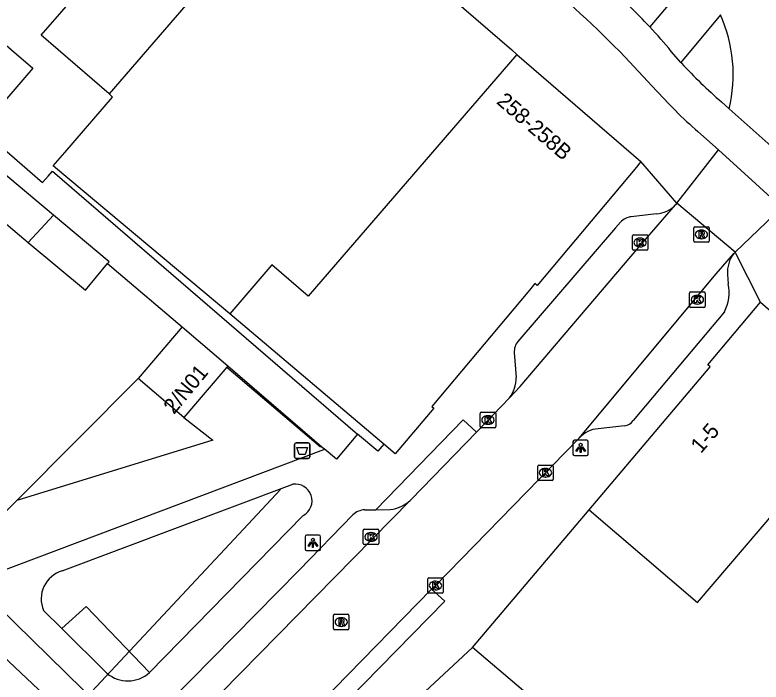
# Model space of a CAD drawing. Extents: x 162347 to 162868, y 381221 to 381813.
# Drawn here: x 162638.62 to 162687, y 381630.34 to 381673.56 of the extents above; entities that cross this region are included whole.
import ezdxf

# ---------------------------------------------------------------- set-up
doc = ezdxf.new("R2010")
doc.units = 0
for name, color, linetype in [('IMGEO_Afvalbak', 7, 'Continuous'), ('IMGEO_Fietspad_gesloten', 7, 'Continuous'), ('IMGEO_Groenvoorziening', 7, 'Continuous'), ('IMGEO_Hek', 7, 'Continuous'), ('IMGEO_Kolk', 7, 'Continuous'), ('IMGEO_Lichtpunt', 7, 'Continuous'), ('IMGEO_Pand', 7, 'Continuous'), ('IMGEO_Pand_nummerreeks', 7, 'Continuous'), ('IMGEO_Rijbaan_lokaal_gesloten', 7, 'Continuous'), ('IMGEO_Rijbaan_lokaal_open', 7, 'Continuous'), ('IMGEO_Rioolput', 7, 'Continuous'), ('IMGEO_Voetpad_open', 7, 'Continuous')]:
    doc.layers.add(name, color=color, linetype=linetype)

msp = doc.modelspace()

# ---------------------------------------------------------------- linework, layer by layer
at = {"layer": 'IMGEO_Afvalbak'}
for p, q in [((162656.75, 381644.93), (162656.75, 381645.73)), ((162656.75, 381645.73), (162656.75, 381644.93)), ((162656.85, 381645.83), (162657.64, 381645.83)), ((162657.64, 381645.83), (162656.85, 381645.83)), ((162657.74, 381645.73), (162657.74, 381644.93)), ((162657.74, 381644.93), (162657.74, 381645.73)), ((162657.64, 381644.83), (162656.85, 381644.83)), ((162656.85, 381644.83), (162657.64, 381644.83))]:
    msp.add_line(p, q, dxfattribs=at)
msp.add_lwpolyline([(162656.893, 381645.544), (162657.597, 381645.544), (162657.448, 381645.074), (162657.042, 381645.074), (162656.893, 381645.544)], dxfattribs=at)
for centre, start, end in [((162656.85, 381645.73), 90, 180), ((162656.85, 381645.73), 90, 180), ((162657.64, 381645.73), 0, 90), ((162657.64, 381645.73), 360, 90), ((162656.85, 381644.93), 180, 270), ((162656.85, 381644.93), 180, 270), ((162657.64, 381644.93), 270, 0), ((162657.64, 381644.93), 270, 0)]:
    msp.add_arc(centre, 0.1, start, end, dxfattribs=at)
at = {"layer": 'IMGEO_Fietspad_gesloten'}
for points in [[(162681.795, 381670.488), (162681.178, 381671.194)], [(162680.247, 381668.629), (162678.17, 381670.854)], [(162681.84, 381670.436), (162681.795, 381670.488)], [(162684.935, 381667.487), (162684.428, 381667.923)], [(162684.232, 381664.825), (162683.099, 381665.838)]]:
    msp.add_lwpolyline(points, dxfattribs=at)
for centre, radius, start, end in [((162612.48, 381606.111), 92.232, 44.58423, 49.55754), ((162653.024, 381647.945), 36.514, 42.8755, 48.9472), ((162652.152, 381647.216), 37.649, 39.5606, 42.7858), ((162707.177, 381693.941), 34.561, 222.8508, 228.8339), ((162701.917, 381687.92), 29.013, 221.676, 229.5626)]:
    msp.add_arc(centre, radius, start, end, dxfattribs=at)
at = {"layer": 'IMGEO_Groenvoorziening'}
for points in [[(162646.61, 381650.012), (162638.739, 381642.093)], [(162649.564, 381647.48), (162651.445, 381646.012), (162638.739, 381642.093)], [(162638.739, 381642.093), (162637.13, 381640.474), (162633.056, 381636.194)], [(162647.35, 381630.961), (162643.234, 381635.23), (162641.661, 381633.808)]]:
    msp.add_lwpolyline(points, dxfattribs=at)
at = {"layer": 'IMGEO_Hek'}
for points in [[(162652.358, 381650.739), (162658.431, 381645.579)], [(162655.842, 381642.815), (162652.232, 381638.954)], [(162652.232, 381638.954), (162642.062, 381628.072), (162636.69, 381633.102)]]:
    msp.add_lwpolyline(points, dxfattribs=at)
at = {"layer": 'IMGEO_Kolk'}
for p, q in [((162678.652, 381658.392), (162678.652, 381659.244)), ((162678.727, 381659.318), (162679.579, 381659.318)), ((162679.14, 381659.098), (162679.165, 381659.098)), ((162679.653, 381659.244), (162679.653, 381658.392)), ((162679.163, 381658.538), (162679.138, 381658.538)), ((162679.579, 381658.318), (162678.727, 381658.318)), ((162682.442, 381655.611), (162683.294, 381655.611)), ((162682.367, 381654.685), (162682.367, 381655.537)), ((162682.855, 381655.391), (162682.88, 381655.391)), ((162683.368, 381655.537), (162683.368, 381654.685)), ((162683.294, 381654.611), (162682.442, 381654.611)), ((162682.878, 381654.831), (162682.853, 381654.831)), ((162668.791, 381646.891), (162668.791, 381647.743)), ((162668.866, 381647.817), (162669.718, 381647.817)), ((162669.279, 381647.597), (162669.304, 381647.597)), ((162669.792, 381647.743), (162669.792, 381646.891)), ((162669.302, 381647.037), (162669.277, 381647.037)), ((162669.718, 381646.817), (162668.866, 381646.817)), ((162672.522, 381643.474), (162672.522, 381644.326)), ((162672.597, 381644.4), (162673.449, 381644.4)), ((162673.01, 381644.18), (162673.035, 381644.18)), ((162673.523, 381644.326), (162673.523, 381643.474)), ((162673.033, 381643.62), (162673.008, 381643.62)), ((162673.449, 381643.4), (162672.597, 381643.4)), ((162661.209, 381639.316), (162661.209, 381640.168)), ((162661.284, 381640.242), (162662.136, 381640.242)), ((162662.21, 381640.168), (162662.21, 381639.316)), ((162661.697, 381640.022), (162661.722, 381640.022)), ((162662.136, 381639.242), (162661.284, 381639.242)), ((162661.72, 381639.462), (162661.695, 381639.462)), ((162665.39, 381636.169), (162665.39, 381637.021)), ((162665.465, 381637.095), (162666.317, 381637.095)), ((162665.878, 381636.875), (162665.903, 381636.875)), ((162666.391, 381637.021), (162666.391, 381636.169)), ((162665.901, 381636.315), (162665.876, 381636.315)), ((162666.317, 381636.095), (162665.465, 381636.095))]:
    msp.add_line(p, q, dxfattribs=at)
for points in [[(162678.652, 381658.392), (162678.652, 381659.244)], [(162678.727, 381659.318), (162679.579, 381659.318)], [(162678.973, 381659.018), (162679.096, 381659.018), (162679.096, 381658.867), (162679.226, 381659.018), (162679.39, 381659.018), (162679.244, 381658.867), (162679.397, 381658.618), (162679.245, 381658.618), (162679.16, 381658.782), (162679.096, 381658.715), (162679.096, 381658.618), (162678.973, 381658.618), (162678.973, 381659.018)], [(162679.653, 381659.244), (162679.653, 381658.392)], [(162679.579, 381658.318), (162678.727, 381658.318)], [(162682.442, 381655.611), (162683.294, 381655.611)], [(162682.367, 381654.685), (162682.367, 381655.537)], [(162682.688, 381655.311), (162682.811, 381655.311), (162682.811, 381655.16), (162682.941, 381655.311), (162683.105, 381655.311), (162682.959, 381655.16), (162683.112, 381654.911), (162682.96, 381654.911), (162682.875, 381655.075), (162682.811, 381655.008), (162682.811, 381654.911), (162682.688, 381654.911), (162682.688, 381655.311)], [(162683.368, 381655.537), (162683.368, 381654.685)], [(162683.294, 381654.611), (162682.442, 381654.611)], [(162668.791, 381646.891), (162668.791, 381647.743)], [(162668.866, 381647.817), (162669.718, 381647.817)], [(162669.112, 381647.517), (162669.235, 381647.517), (162669.235, 381647.366), (162669.365, 381647.517), (162669.529, 381647.517), (162669.383, 381647.366), (162669.536, 381647.117), (162669.384, 381647.117), (162669.299, 381647.281), (162669.235, 381647.214), (162669.235, 381647.117), (162669.112, 381647.117), (162669.112, 381647.517)], [(162669.792, 381647.743), (162669.792, 381646.891)], [(162669.718, 381646.817), (162668.866, 381646.817)], [(162672.522, 381643.474), (162672.522, 381644.326)], [(162672.597, 381644.4), (162673.449, 381644.4)], [(162672.843, 381644.1), (162672.966, 381644.1), (162672.966, 381643.949), (162673.096, 381644.1), (162673.26, 381644.1), (162673.114, 381643.949), (162673.267, 381643.7), (162673.115, 381643.7), (162673.03, 381643.864), (162672.966, 381643.797), (162672.966, 381643.7), (162672.843, 381643.7), (162672.843, 381644.1)], [(162673.523, 381644.326), (162673.523, 381643.474)], [(162673.449, 381643.4), (162672.597, 381643.4)], [(162661.209, 381639.316), (162661.209, 381640.168)], [(162661.284, 381640.242), (162662.136, 381640.242)], [(162662.21, 381640.168), (162662.21, 381639.316)], [(162661.53, 381639.942), (162661.653, 381639.942), (162661.653, 381639.791), (162661.783, 381639.942), (162661.947, 381639.942), (162661.801, 381639.791), (162661.954, 381639.542), (162661.802, 381639.542), (162661.717, 381639.706), (162661.653, 381639.639), (162661.653, 381639.542), (162661.53, 381639.542), (162661.53, 381639.942)], [(162662.136, 381639.242), (162661.284, 381639.242)], [(162665.39, 381636.169), (162665.39, 381637.021)], [(162665.465, 381637.095), (162666.317, 381637.095)], [(162665.711, 381636.795), (162665.834, 381636.795), (162665.834, 381636.644), (162665.964, 381636.795), (162666.128, 381636.795), (162665.982, 381636.644), (162666.135, 381636.395), (162665.983, 381636.395), (162665.898, 381636.559), (162665.834, 381636.492), (162665.834, 381636.395), (162665.711, 381636.395), (162665.711, 381636.795)], [(162666.391, 381637.021), (162666.391, 381636.169)], [(162666.317, 381636.095), (162665.465, 381636.095)]]:
    msp.add_lwpolyline(points, dxfattribs=at)
for centre, start, end in [((162678.729, 381659.242), 91.552, 178.448), ((162678.729, 381659.242), 91.552, 178.448), ((162679.577, 381659.242), 1.552, 88.448), ((162679.577, 381659.242), 1.552, 88.448), ((162678.729, 381658.394), 181.552, 268.448), ((162678.729, 381658.394), 181.552, 268.448), ((162679.577, 381658.394), 271.552, 358.448), ((162679.577, 381658.394), 271.552, 358.448), ((162682.444, 381655.535), 91.552, 178.448), ((162682.444, 381655.535), 91.552, 178.448), ((162683.292, 381655.535), 1.552, 88.448), ((162683.292, 381655.535), 1.552, 88.448), ((162682.444, 381654.687), 181.552, 268.448), ((162682.444, 381654.687), 181.552, 268.448), ((162683.292, 381654.687), 271.552, 358.448), ((162683.292, 381654.687), 271.552, 358.448), ((162668.868, 381647.741), 91.552, 178.448), ((162668.868, 381647.741), 91.552, 178.448), ((162669.716, 381647.741), 1.552, 88.448), ((162669.716, 381647.741), 1.552, 88.448), ((162668.868, 381646.893), 181.552, 268.448), ((162668.868, 381646.893), 181.552, 268.448), ((162669.716, 381646.893), 271.552, 358.448), ((162669.716, 381646.893), 271.552, 358.448), ((162672.599, 381644.324), 91.552, 178.448), ((162672.599, 381644.324), 91.552, 178.448), ((162673.447, 381644.324), 1.552, 88.448), ((162673.447, 381644.324), 1.552, 88.448), ((162672.599, 381643.476), 181.552, 268.448), ((162672.599, 381643.476), 181.552, 268.448), ((162673.447, 381643.476), 271.552, 358.448), ((162673.447, 381643.476), 271.552, 358.448), ((162661.286, 381640.166), 91.552, 178.448), ((162661.286, 381640.166), 91.552, 178.448), ((162662.134, 381640.166), 1.552, 88.448), ((162662.134, 381640.166), 1.552, 88.448), ((162661.286, 381639.318), 181.552, 268.448), ((162661.286, 381639.318), 181.552, 268.448), ((162662.134, 381639.318), 271.552, 358.448), ((162662.134, 381639.318), 271.552, 358.448), ((162665.467, 381637.019), 91.552, 178.448), ((162665.467, 381637.019), 91.552, 178.448), ((162666.315, 381637.019), 1.552, 88.448), ((162666.315, 381637.019), 1.552, 88.448), ((162665.467, 381636.171), 181.552, 268.448), ((162665.467, 381636.171), 181.552, 268.448), ((162666.315, 381636.171), 271.552, 358.448), ((162666.315, 381636.171), 271.552, 358.448)]:
    msp.add_arc(centre, 0.0765, start, end, dxfattribs=at)
for centre, major_axis, ratio, start_param, end_param in [((162679.139, 381658.818), (-0.387, 0.002), 0.722429, 4.712389, 7.853982), ((162679.164, 381658.818), (-0.39, 0.002), 0.717154, 1.570796, 4.712389), ((162682.854, 381655.111), (-0.387, 0.002), 0.722429, 4.712389, 7.853982), ((162682.879, 381655.111), (-0.39, 0.002), 0.717154, 1.570796, 4.712389), ((162669.278, 381647.317), (-0.387, 0.002), 0.722429, 4.712389, 7.853982), ((162669.303, 381647.317), (-0.39, 0.002), 0.717154, 1.570796, 4.712389), ((162673.009, 381643.9), (-0.387, 0.002), 0.722429, 4.712389, 7.853982), ((162673.034, 381643.9), (-0.39, 0.002), 0.717154, 1.570796, 4.712389), ((162661.696, 381639.742), (-0.387, 0.002), 0.722429, 4.712389, 7.853982), ((162661.721, 381639.742), (-0.39, 0.002), 0.717154, 1.570796, 4.712389), ((162665.877, 381636.595), (-0.387, 0.002), 0.722429, 4.712389, 7.853982), ((162665.902, 381636.595), (-0.39, 0.002), 0.717154, 1.570796, 4.712389)]:
    msp.add_ellipse(centre, major_axis=major_axis, ratio=ratio, start_param=start_param, end_param=end_param, dxfattribs=at)
at = {"layer": 'IMGEO_Lichtpunt'}
for p, q in [((162674.802, 381645.911), (162674.802, 381645.104)), ((162674.802, 381645.911), (162674.802, 381645.104)), ((162675.704, 381646.006), (162674.896, 381646.006)), ((162675.704, 381646.006), (162674.896, 381646.006)), ((162675.798, 381645.104), (162675.798, 381645.911)), ((162675.798, 381645.104), (162675.798, 381645.911)), ((162674.896, 381645.01), (162675.704, 381645.01)), ((162674.896, 381645.01), (162675.704, 381645.01)), ((162657.442, 381639.758), (162657.442, 381638.951)), ((162657.442, 381639.758), (162657.442, 381638.951)), ((162658.344, 381639.853), (162657.536, 381639.853)), ((162658.344, 381639.853), (162657.536, 381639.853)), ((162658.438, 381638.951), (162658.438, 381639.758)), ((162658.438, 381638.951), (162658.438, 381639.758)), ((162657.536, 381638.857), (162658.344, 381638.857)), ((162657.536, 381638.857), (162658.344, 381638.857))]:
    msp.add_line(p, q, dxfattribs=at)
for points in [[(162675.176, 381645.575), (162675.215, 381645.547), (162675.027, 381645.285), (162674.989, 381645.312), (162675.176, 381645.575)], [(162675.278, 381645.527), (162675.325, 381645.527), (162675.325, 381645.205), (162675.278, 381645.205), (162675.278, 381645.527)], [(162675.388, 381645.547), (162675.426, 381645.574), (162675.613, 381645.312), (162675.574, 381645.284), (162675.388, 381645.547)], [(162657.816, 381639.422), (162657.855, 381639.394), (162657.667, 381639.132), (162657.629, 381639.159), (162657.816, 381639.422)], [(162657.918, 381639.374), (162657.965, 381639.374), (162657.965, 381639.052), (162657.918, 381639.052), (162657.918, 381639.374)], [(162658.028, 381639.394), (162658.066, 381639.421), (162658.253, 381639.159), (162658.214, 381639.131), (162658.028, 381639.394)]]:
    msp.add_lwpolyline(points, dxfattribs=at)
for centre in [(162675.301, 381645.709), (162657.941, 381639.556)]:
    msp.add_circle(centre, 0.0994, dxfattribs=at)
for centre, start, end in [((162674.896, 381645.911), 90, 180), ((162674.896, 381645.911), 90, 180), ((162675.704, 381645.911), 0, 90), ((162675.704, 381645.911), 0, 90), ((162674.896, 381645.104), 180, 270), ((162674.896, 381645.104), 180, 270), ((162675.704, 381645.104), 270, 0), ((162675.704, 381645.104), 270, 360), ((162657.536, 381639.758), 90, 180), ((162657.536, 381639.758), 90, 180), ((162658.344, 381639.758), 0, 90), ((162658.344, 381639.758), 0, 90), ((162657.536, 381638.951), 180, 270), ((162657.536, 381638.951), 180, 270), ((162658.344, 381638.951), 270, 0), ((162658.344, 381638.951), 270, 360)]:
    msp.add_arc(centre, 0.0946, start, end, dxfattribs=at)
at = {"layer": 'IMGEO_Pand'}
for points in [[(162644.725, 381668.442), (162640.323, 381672.242), (162642.842, 381675.159), (162644.71, 381677.345), (162648.449, 381681.676), (162649.606, 381683.017), (162652.873, 381686.801)], [(162657.285, 381682.992), (162644.725, 381668.442)], [(162657.285, 381682.992), (162657.765, 381682.579), (162670.832, 381671.299), (162671.169, 381671.008)], [(162637.043, 381672.476), (162638.402, 381671.303), (162639.79, 381670.105), (162637.974, 381668.001), (162636.665, 381666.484), (162633.916, 381668.861)], [(162671.169, 381671.008), (162657.64, 381655.334), (162655.287, 381657.365), (162652.558, 381654.203)], [(162671.169, 381671.008), (162679.213, 381664.065)], [(162652.558, 381654.203), (162641.244, 381663.665), (162641.107, 381663.78), (162641.857, 381664.649), (162644.958, 381668.241), (162644.725, 381668.442)], [(162679.213, 381664.065), (162678.918, 381663.694), (162672.478, 381656.041), (162672.34, 381656.157), (162671.986, 381655.736), (162665.642, 381648.188), (162665.772, 381648.078), (162663.268, 381645.119), (162662.532, 381645.744)], [(162637.535, 381663.439), (162636.064, 381661.68), (162639.487, 381658.819)], [(162641.133, 381660.582), (162637.609, 381663.528), (162637.535, 381663.439)], [(162639.487, 381658.819), (162641.133, 381660.582)], [(162644.628, 381657.449), (162644.732, 381657.574), (162641.133, 381660.582)], [(162639.487, 381658.819), (162643.187, 381655.726), (162644.628, 381657.449)], [(162675.845, 381641.49), (162683.699, 381650.754), (162683.556, 381650.896), (162686.96, 381654.957)], [(162686.96, 381654.957), (162694.188, 381648.719)], [(162662.532, 381645.744), (162652.841, 381653.967), (162652.558, 381654.203)], [(162649.475, 381653.355), (162646.61, 381650.012)], [(162649.475, 381653.355), (162652.429, 381650.823)], [(162652.429, 381650.823), (162652.358, 381650.739), (162650.946, 381649.092), (162649.564, 381647.48)], [(162649.564, 381647.48), (162646.61, 381650.012)], [(162675.845, 381641.49), (162682.884, 381635.503), (162694.188, 381648.719)], [(162668.299, 381632.588), (162675.845, 381641.49)], [(162692.852, 381627.024), (162690.819, 381628.753), (162683.248, 381619.871), (162668.299, 381632.588)]]:
    msp.add_lwpolyline(points, dxfattribs=at)
at = {"layer": 'IMGEO_Rijbaan_lokaal_gesloten'}
for points in [[(162684.935, 381667.487), (162690.775, 381662.288)], [(162681.539, 381661.361), (162682.168, 381662.17), (162684.232, 381664.825)], [(162684.232, 381664.825), (162688.355, 381661.085)], [(162685.311, 381658.19), (162681.539, 381661.361)], [(162688.355, 381661.085), (162685.311, 381658.19)]]:
    msp.add_lwpolyline(points, dxfattribs=at)
msp.add_arc((162675.681, 381669.685), 9.512, 346.6378, 24.047, dxfattribs=at)
at = {"layer": 'IMGEO_Rijbaan_lokaal_open'}
for points in [[(162670.68, 381648.753), (162671.388, 381649.497), (162679.069, 381658.505), (162681.453, 381661.251)], [(162681.539, 381661.361), (162681.453, 381661.251)], [(162675.203, 381646.144), (162684.096, 381656.787), (162685.234, 381658.098)], [(162685.234, 381658.098), (162685.311, 381658.19)], [(162670.68, 381648.753), (162668.538, 381646.537)], [(162668.538, 381646.537), (162664.319, 381642.173), (162664.256, 381642.113)], [(162665.637, 381636.368), (162665.891, 381636.595), (162675.14, 381646.068), (162675.203, 381646.144)], [(162664.256, 381642.113), (162647.112, 381624.677)], [(162654.327, 381624.795), (162659.336, 381629.932), (162665.637, 381636.368)], [(162660.865, 381625.672), (162663.359, 381627.992), (162668.299, 381632.588)]]:
    msp.add_lwpolyline(points, dxfattribs=at)
at = {"layer": 'IMGEO_Rioolput'}
for p, q in [((162682.633, 381658.912), (162682.633, 381659.764)), ((162682.708, 381659.838), (162683.56, 381659.838)), ((162683.121, 381659.618), (162683.146, 381659.618)), ((162683.634, 381659.764), (162683.634, 381658.912)), ((162683.144, 381659.058), (162683.119, 381659.058)), ((162683.56, 381658.838), (162682.708, 381658.838)), ((162659.277, 381633.802), (162659.277, 381634.654)), ((162659.352, 381634.728), (162660.204, 381634.728)), ((162659.765, 381634.508), (162659.79, 381634.508)), ((162660.278, 381634.654), (162660.278, 381633.802)), ((162659.788, 381633.948), (162659.763, 381633.948)), ((162660.204, 381633.728), (162659.352, 381633.728))]:
    msp.add_line(p, q, dxfattribs=at)
for points in [[(162682.633, 381658.912), (162682.633, 381659.764)], [(162682.708, 381659.838), (162683.56, 381659.838)], [(162683.222, 381659.536), (162682.97, 381659.538), (162682.97, 381659.138)], [(162683.148, 381659.457), (162683.094, 381659.457), (162683.094, 381659.376)], [(162683.634, 381659.764), (162683.634, 381658.912)], [(162682.97, 381659.138), (162683.094, 381659.138), (162683.094, 381659.3), (162683.105, 381659.3)], [(162683.094, 381659.376), (162683.146, 381659.376)], [(162683.152, 381659.271), (162683.223, 381659.138), (162683.363, 381659.138), (162683.298, 381659.264)], [(162683.56, 381658.838), (162682.708, 381658.838)], [(162659.277, 381633.802), (162659.277, 381634.654)], [(162659.352, 381634.728), (162660.204, 381634.728)], [(162659.866, 381634.426), (162659.614, 381634.428), (162659.614, 381634.028)], [(162659.792, 381634.347), (162659.738, 381634.347), (162659.738, 381634.266)], [(162660.278, 381634.654), (162660.278, 381633.802)], [(162659.614, 381634.028), (162659.738, 381634.028), (162659.738, 381634.19), (162659.749, 381634.19)], [(162659.738, 381634.266), (162659.79, 381634.266)], [(162659.796, 381634.161), (162659.867, 381634.028), (162660.007, 381634.028), (162659.942, 381634.154)], [(162660.204, 381633.728), (162659.352, 381633.728)]]:
    msp.add_lwpolyline(points, dxfattribs=at)
for centre, radius, start, end in [((162682.71, 381659.762), 0.0765, 91.552, 178.448), ((162682.71, 381659.762), 0.0765, 91.552, 178.448), ((162683.154, 381659.361), 0.0964, 77.0061, 93.1865), ((162683.168, 381659.418), 0.0378, 276.6634, 79.6772), ((162683.221, 381659.426), 0.109, 350.3612, 89.416), ((162683.558, 381659.762), 0.0765, 1.552, 88.448), ((162683.558, 381659.762), 0.0765, 1.552, 88.448), ((162683.104, 381659.247), 0.0533, 26.0293, 88.6989), ((162683.13, 381659.565), 0.19, 274.7715, 282.9687), ((162683.219, 381659.426), 0.112, 277.5842, 350.9817), ((162683.203, 381659.211), 0.108, 29.5134, 73.7905), ((162682.71, 381658.914), 0.0765, 181.552, 268.448), ((162682.71, 381658.914), 0.0765, 181.552, 268.448), ((162683.558, 381658.914), 0.0765, 271.552, 358.448), ((162683.558, 381658.914), 0.0765, 271.552, 358.448), ((162659.354, 381634.652), 0.0765, 91.552, 178.448), ((162659.354, 381634.652), 0.0765, 91.552, 178.448), ((162659.798, 381634.251), 0.0964, 77.0061, 93.1865), ((162659.812, 381634.308), 0.0378, 276.6634, 79.6772), ((162659.865, 381634.316), 0.109, 350.3612, 89.416), ((162659.863, 381634.316), 0.112, 277.5842, 350.9817), ((162660.202, 381634.652), 0.0765, 1.552, 88.448), ((162660.202, 381634.652), 0.0765, 1.552, 88.448), ((162659.354, 381633.804), 0.0765, 181.552, 268.448), ((162659.354, 381633.804), 0.0765, 181.552, 268.448), ((162659.748, 381634.137), 0.0533, 26.0293, 88.6989), ((162659.774, 381634.455), 0.19, 274.7715, 282.9687), ((162659.847, 381634.101), 0.108, 29.5134, 73.7905), ((162660.202, 381633.804), 0.0765, 271.552, 358.448), ((162660.202, 381633.804), 0.0765, 271.552, 358.448)]:
    msp.add_arc(centre, radius, start, end, dxfattribs=at)
for centre, major_axis, ratio, start_param, end_param in [((162683.12, 381659.338), (-0.387, 0.002), 0.722429, 4.712389, 7.853982), ((162683.145, 381659.338), (-0.39, 0.002), 0.717154, 1.570796, 4.712389), ((162659.764, 381634.228), (-0.387, 0.002), 0.722429, 4.712389, 7.853982), ((162659.789, 381634.228), (-0.39, 0.002), 0.717154, 1.570796, 4.712389)]:
    msp.add_ellipse(centre, major_axis=major_axis, ratio=ratio, start_param=start_param, end_param=end_param, dxfattribs=at)
at = {"layer": 'IMGEO_Voetpad_open'}
for points in [[(162615.01, 381684.77), (162635.091, 381667.467), (162636.457, 381666.288), (162636.428, 381666.14), (162640.413, 381662.701), (162640.768, 381663.113), (162641.053, 381663.444), (162660.838, 381646.394)], [(162682.633, 381676.178), (162679.783, 381672.789)], [(162684.367, 381673.561), (162681.795, 381670.488)], [(162681.539, 381661.361), (162679.213, 381664.065)], [(162680.217, 381660.669), (162678.581, 381660.491)], [(162677.886, 381660.139), (162677.552, 381659.762), (162671.237, 381652.407)], [(162686.96, 381654.957), (162685.311, 381658.19)], [(162644.628, 381657.449), (162649.475, 381653.355)], [(162684.814, 381656.747), (162684.865, 381656.143)], [(162684.618, 381654.325), (162678.708, 381647.284)], [(162670.999, 381651.685), (162671.113, 381650.07)], [(162652.429, 381650.823), (162658.671, 381645.439)], [(162662.03, 381641.507), (162667.683, 381647.337), (162668.538, 381646.537)], [(162678.149, 381646.936), (162676.443, 381646.753)], [(162660.838, 381646.394), (162659.465, 381644.774), (162658.671, 381645.439)], [(162662.532, 381645.744), (162662.142, 381645.292), (162660.838, 381646.394)], [(162658.671, 381645.439), (162658.632, 381645.394), (162633.394, 381635.882)], [(162641.683, 381637.54), (162656.632, 381643.15)], [(162657.312, 381641.139), (162647.35, 381630.961)], [(162647.913, 381628.318), (162650.017, 381630.457), (162657.042, 381637.598), (162660.527, 381641.166)], [(162661.309, 381641.5), (162662.03, 381641.507)], [(162662.03, 381641.507), (162662.958, 381641.516)], [(162665.637, 381636.368), (162666.501, 381635.573), (162660.187, 381629.138), (162655.332, 381623.81), (162654.327, 381624.795)], [(162637.524, 381635.211), (162645.202, 381627.721), (162644.357, 381626.848), (162641.025, 381623.407)], [(162641.661, 381633.808), (162640.478, 381634.982)], [(162644.579, 381630.912), (162641.661, 381633.808)]]:
    msp.add_lwpolyline(points, dxfattribs=at)
for centre, radius, start, end in [((162680.001, 381662.732), 2.074, 275.9848, 314.4442), ((162678.738, 381659.318), 1.183, 97.6365, 136.0856), ((162686.812, 381656.867), 2.001, 142.0305, 183.4305), ((162682.461, 381655.544), 2.477, 330.5281, 13.9978), ((162672.002, 381651.755), 1.005, 139.5391, 183.9724), ((162669.164, 381649.981), 1.951, 320.9892, 2.6114), ((162678.063, 381647.697), 0.766, 276.4458, 327.362), ((162676.566, 381644.936), 1.821, 93.8641, 138.4499), ((162656.811, 381642.09), 1.075, 297.7963, 99.5687), ((162662.669, 381643.853), 2.355, 277.0405, 312.3585), ((162661.349, 381640.323), 1.177, 91.9598, 134.2958), ((162642.199, 381635.734), 1.878, 105.9476, 203.6049), ((162645.937, 381632.513), 2.099, 229.6987, 312.3274)]:
    msp.add_arc(centre, radius, start, end, dxfattribs=at)

# ---------------------------------------------------------------- texts
at = {"layer": 'IMGEO_Pand_nummerreeks'}
for s, rotation, p in [('258-258B', 319.1997, (162669.786, 381667.869)), ('2/N01', 50.1479, (162648.93, 381647.636)), ('1-5', 49.1483, (162683.095, 381645.102))]:
    msp.add_text(s, height=1, rotation=rotation, dxfattribs=at).set_placement(p)

doc.saveas('drawing.dxf')
